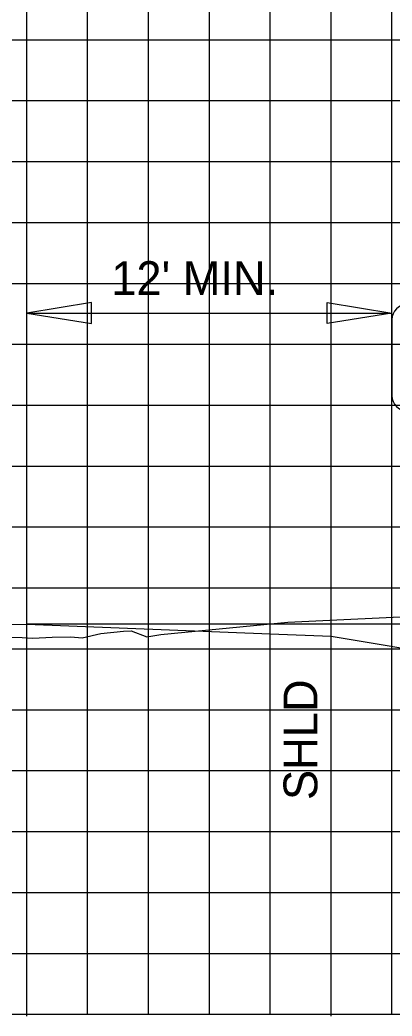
# Model space of a CAD drawing. Extents: x 2193008 to 2198143, y 1236112 to 1237864.
# Drawn here: x 2195072.63 to 2195084.86, y 1237163.05 to 1237195.76 of the extents above; entities that cross this region are included whole.
import ezdxf

# ---------------------------------------------------------------- set-up
doc = ezdxf.new("R2010")
doc.units = 0
for name, color, linetype in [('3', 7, 'Continuous'), ('60', 7, 'Continuous'), ('GSCOLORFILL', 7, 'Continuous'), ('GSDIMS', 7, 'Continuous'), ('Level 55', 7, 'Continuous'), ('Level 61', 7, 'Continuous'), ('M-ROADS', 7, 'Continuous')]:
    doc.layers.add(name, color=color, linetype=linetype)

msp = doc.modelspace()

# ---------------------------------------------------------------- linework, layer by layer
at = {"layer": '3'}
msp.add_line((2195072.86, 1237175.918), (2195072.86, 1237187.325), dxfattribs=at)
at = {"layer": '60'}
for p, q in [((2195042.86, 1237163.106), (2195172.86, 1237163.106)), ((2195072.86, 1237163.046), (2195072.86, 1237163.106)), ((2195082.86, 1237163.046), (2195082.86, 1237163.106))]:
    msp.add_line(p, q, dxfattribs=at)
msp.add_lwpolyline([(2195046.858, 1237176.044), (2195051.855, 1237175.844), (2195052.185, 1237175.844), (2195052.352, 1237175.344), (2195054.352, 1237175.511), (2195056.86, 1237175.566), (2195072.86, 1237175.918), (2195080.86, 1237175.598), (2195082.86, 1237175.518), (2195094.86, 1237173.518), (2195097.86, 1237173.518), (2195105.244, 1237175.364)], dxfattribs=at)
at = {"layer": 'GSCOLORFILL'}
msp.add_line((2195084.86, 1237185.915), (2195084.86, 1237183.418), dxfattribs=at)
for centre, start, end in [((2195085.36, 1237185.915), 90, 180), ((2195085.36, 1237183.418), 180, 270)]:
    msp.add_arc(centre, 0.5, start, end, dxfattribs=at)
at = {"layer": 'GSDIMS'}
for p, q in [((2195085.931, 1237175.918), (2195072.86, 1237175.918)), ((2195082.86, 1237170.104), (2195082.86, 1237175.518))]:
    msp.add_line(p, q, dxfattribs=at)
for points in [[(2195072.86, 1237186.131), (2195074.989, 1237185.783), (2195074.989, 1237186.478)], [(2195084.86, 1237186.131), (2195082.732, 1237185.783), (2195082.732, 1237186.478)]]:
    msp.add_lwpolyline(points, close=True, dxfattribs=at)
at = {"layer": 'Level 61'}
msp.add_line((2195072.86, 1237186.131), (2195084.86, 1237186.131), dxfattribs=at)
at = {"layer": 'M-ROADS'}
for p, q in [((2195072.86, 1237163.106), (2195072.86, 1237223.106)), ((2195074.86, 1237163.106), (2195074.86, 1237223.106)), ((2195076.86, 1237163.106), (2195076.86, 1237223.106)), ((2195078.86, 1237163.106), (2195078.86, 1237223.106)), ((2195080.86, 1237163.106), (2195080.86, 1237223.106)), ((2195082.86, 1237163.106), (2195082.86, 1237223.106)), ((2195084.86, 1237163.106), (2195084.86, 1237223.106)), ((2195042.86, 1237195.106), (2195172.86, 1237195.106)), ((2195042.86, 1237193.106), (2195172.86, 1237193.106)), ((2195042.86, 1237191.106), (2195172.86, 1237191.106)), ((2195042.86, 1237189.106), (2195172.86, 1237189.106)), ((2195042.86, 1237187.106), (2195172.86, 1237187.106)), ((2195042.86, 1237185.106), (2195172.86, 1237185.106)), ((2195042.86, 1237183.106), (2195172.86, 1237183.106)), ((2195042.86, 1237181.106), (2195172.86, 1237181.106)), ((2195042.86, 1237179.106), (2195172.86, 1237179.106)), ((2195042.86, 1237177.106), (2195172.86, 1237177.106)), ((2195042.86, 1237175.106), (2195172.86, 1237175.106)), ((2195042.86, 1237173.106), (2195172.86, 1237173.106)), ((2195042.86, 1237171.106), (2195172.86, 1237171.106)), ((2195042.86, 1237169.106), (2195172.86, 1237169.106)), ((2195042.86, 1237167.106), (2195172.86, 1237167.106)), ((2195042.86, 1237165.106), (2195172.86, 1237165.106)), ((2195042.86, 1237163.106), (2195172.86, 1237163.106))]:
    msp.add_line(p, q, dxfattribs=at)
msp.add_lwpolyline([(2195071.807, 1237175.5), (2195072.71, 1237175.478), (2195073.058, 1237175.457), (2195073.696, 1237175.487), (2195074.307, 1237175.503), (2195074.677, 1237175.461), (2195075.296, 1237175.609), (2195076.038, 1237175.683), (2195076.291, 1237175.694), (2195076.804, 1237175.503), (2195077.269, 1237175.577), (2195081.441, 1237175.981), (2195086.277, 1237176.206)], dxfattribs=at)

# ---------------------------------------------------------------- texts
at = {"layer": 'Level 55'}
msp.add_text("12' MIN.", height=1.1105, dxfattribs=at).set_placement((2195075.638, 1237186.723))
msp.add_text('SHLD', height=1.1105, rotation=90, dxfattribs=at).set_placement((2195082.408, 1237170.14))

doc.saveas('drawing.dxf')
